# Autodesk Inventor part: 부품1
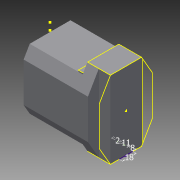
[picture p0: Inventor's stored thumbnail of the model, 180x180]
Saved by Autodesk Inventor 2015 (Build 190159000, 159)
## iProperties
Created: 2023-05
Part Number: 부품1
Material: 일반
Document SubType Name: Modeling
Designer: 102566
Density: 1 g/cm^3
Appearance: 기본값
Author: 102566
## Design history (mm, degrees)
sketch "스케치1"
  geometry: L1 (-35, -40)-(35, -40); L2 (35, -40)-(35, 40); L3 (35, 40)-(-35, 40); L4 (-35, 40)-(-35, -40); L5 (-35, -40)-(35, 40); L6 (35, -40)-(-35, 40); 1 further point
  constraints: 12 end point, 2 midpoint, 2 parallel, 1 horizontal, 1 perpendicular
  dimensions: "d0" = 70 distance of L3.end L2.end; "d1" = 80 distance of L2.end L1.end
extrude "돌출1" new body sketch "스케치1" distance "d2" = 70; taper "d3" = 0 deg
sketch "스케치2"
  geometry: L1 (40, 35)-(-40, 35) reference; L2 (-40, 35)-(-40, -35) reference; L3 (-40, -35)-(40, -35) reference; L4 (0, 35)-(-26, 35); L5 (-26, 35)-(-40, 26.917); L6 (0, -35)-(-26, -35); L7 (-26, -35)-(-40, -26.917); 1 further point
  constraints: 8 end point, 4 point on line, 2 midpoint
  dimensions: "d4" = 26 distance of L4.start L4.end; "d5" = 30 deg angle of L1 L5; "d6" = 26 distance of L6.start L6.end; "d7" = 30 deg angle of L3 L7
extrude "돌출2" cut sketch "스케치2" stored distance "d8" = 70; taper "d9" = 0 deg
sketch "스케치3"
  geometry: 1 further point
hole "구멍1" sketch "스케치3" at (0, 0) diameter "d10" = 60; stored, may be unused: countersink angle "d14" = 90 deg, drill point angle "d16" = 0 deg; dims "d11" = 6, "d12" = 4, "d13" = 2, "d15" = 5.8
sketch "스케치4"
  geometry: C1 r 30 at (0, 0) reference
hole "구멍2" sketch "스케치4" at (0, 0) diameter "d17" = 60; stored, may be unused: countersink angle "d21" = 90 deg, drill point angle "d23" = 0 deg; dims "d18" = 6, "d19" = 63, "d20" = 2.2, "d22" = 6
sketch "스케치5"
  geometry: 1 further point
sketch "스케치6"
  geometry: L1 (-8, -30)-(-8, -31.5) reference; L2 (-8, -31.5)-(-5.8, -31.5) reference; L3 (-5.8, -31.5)-(-5.8, -30) reference; L4 (-5.8, -30)-(0, -30) reference; L5 (0, -30)-(0, -40) reference; L6 (0, -40)-(-70, -40) reference; L7 (-70, -40)-(-70, 40) reference; L8 (-70, 40)-(0, 40) reference; L9 (0, 40)-(0, 30) reference; L10 (0, 30)-(-5.8, 30) reference; L11 (-5.8, 30)-(-5.8, 31.5) reference; L12 (-5.8, 31.5)-(-8, 31.5) reference; L13 (-8, 31.5)-(-8, 30) reference; L14 (-8, 30)-(-14, 30) reference; L15 (-14, 30)-(-14, -30) reference; L16 (-14, -30)-(-8, -30) reference; L17 (-70, -26)-(-70, 26) reference; L18 (-70, 0)-(0, 0); L19 (-14, -30)-(-14, 30) reference; L20 (-14, 0)-(-14, 25.786); L21 (-14, 25.786)-(-16.158, 25); L22 (-16.158, 25)-(-16.158, 0); L23 (-16.158, 0)-(-14, 0); 2 further points
  constraints: 10 end point, 4 midpoint, 2 point on line, 1 collinear, 1 horizontal, 1 perpendicular, 1 vertical alignment
  dimensions: "d27" = 2.15848 distance between parallel lines of L15 L22; "d28" = 25 distance of L21.end L22.end
revolve "회전1" sketch "스케치6" stored, may be unused: angle "d29" = 90 deg
sketch "스케치7"
  geometry: C1 r 25 at (0, 0) reference; C2 r 25 at (0, 0)
  constraints: 1 centre point, 1 coincident
  dimensions: "d30" = 50 diameter of C2
extrude "돌출3" cut sketch "스케치7" distance "d31" = 42.842; taper "d32" = 0 deg
sketch "스케치8"
  geometry: 1 further point
sketch "스케치9"
  geometry: 1 further point
sketch "스케치10"
  geometry: L1 (40, 26.917)-(26, 35) reference; L2 (26, 35)-(-26, 35) reference; L3 (-26, 35)-(-40, 26.917) reference; L4 (-40, 26.917)-(-40, -26.917) reference; L5 (-40, -26.917)-(-26, -35) reference; L6 (26, -35)-(40, -26.917) reference; L7 (40, -26.917)-(40, 26.917) reference; L8 (-26, 35)-(26, 35); L9 (51, 20.566)-(51, -20.566); L10 (26, -35)-(-26, -35); L11 (-51, -20.566)-(-51, 20.566); L12 (-51, 35)-(51, -35); L13 (51, 35)-(-51, -35); L14 (40, -26.917)-(51, -20.566); L15 (40, 26.917)-(51, 20.566); L16 (-40, -26.917)-(-51, -20.566); L17 (-40, 26.917)-(-51, 20.566); L18 (-40, 26.917)-(-26, 35) reference; C1 r 30 at (0, 0) reference; 1 further point
  constraints: 20 end point, 5 point on line, 2 midpoint, 2 parallel, 1 collinear, 1 horizontal, 1 perpendicular
  dimensions: "d33" = 102 distance of L12.end L13.end; "d34" = 60 deg angle of L15 L14; "d35" = 51 distance from line of point (0, 0) L9; "d36" = 60 deg angle of L17 L16; "d37" = 51 distance from line of point (0, 0) L11; "d38" = 35 distance from line of C1.centre L8
extrude "돌출4" join sketch "스케치10" distance "d39" = 30; taper "d40" = 0 deg
sketch "스케치11"
  geometry: L1 (70, 53.834)-(70, 0) reference; L2 (70, 0)-(0, 0) reference; L3 (70, 53.834)-(64, 53.834); L4 (64, 53.834)-(64, 0); L5 (64, 0)-(70, 0); L6 (70, 0)-(70, 53.834); 1 further point
  constraints: 8 end point, 2 parallel, 1 horizontal, 1 perpendicular, 1 point on line
  dimensions: "d41" = 6 distance of L5.end L4.end
extrude "돌출5" join sketch "스케치11" distance "d42" = 2; taper "d43" = 0 deg
sketch "스케치12"
  geometry: L1 (26, -35)-(51, -20.566) reference; L2 (51, -20.566)-(51, 20.566) reference; L3 (51, 20.566)-(26, 35) reference; L4 (26, 35)-(-26, 35) reference; L5 (-26, 35)-(-51, 20.566) reference; L6 (-51, 20.566)-(-51, -20.566) reference; L7 (-51, -20.566)-(-26, -35) reference; L8 (-26, -35)-(26, -35) reference; 1 further point
sketch "스케치13"
  geometry: L1 (30, 41.132)-(30, 0) reference; L2 (30, 42.566)-(30, -1.434); L3 (30, 42.566)-(15, 42.566); L4 (15, 42.566)-(15, 55.566); L5 (-70, 55.566)-(30, 55.566) reference; L6 (30, 42.566)-(30, 55.566); L7 (30, 55.566)-(30, 41.132) reference; 2 further points
  constraints: 8 end point, 2 midpoint, 1 collinear, 1 horizontal, 1 perpendicular, 1 point on line, 1 vertical
  dimensions: "d44" = 44 distance of L2.start L2.end; "d45" = 15 distance of L2.start L3.end
extrude "돌출6" cut sketch "스케치13" stored distance "d46" = 2; taper "d47" = 0 deg
sketch "스케치14"
  geometry: L1 (70, 53.834)-(64, 53.834) reference; L2 (64, 53.834)-(64, 0) reference; L3 (64, 0)-(70, 0) reference; L4 (70, 0)-(70, 1.155) reference; L5 (70, 52.679)-(70, 1.155) reference; L6 (70, 52.679)-(70, 53.834) reference; 1 further point
sketch "스케치15"
  geometry: L1 (0, 41.132)-(0, 0) reference; L2 (0, 0)-(30, 0) reference; L3 (30, 41.132)-(30, 0) reference; L4 (0, 41.132)-(30, 41.132) reference; 1 further point
sketch "스케치16"
  geometry: L1 (48.517, 22)-(-48.517, 22) reference; L2 (-48.517, 22)-(-51, 20.566) reference; L3 (-51, 20.566)-(-51, -20.566) reference; L4 (-51, -20.566)-(-26, -35) reference; L5 (-26, -35)-(26, -35) reference; L6 (26, -35)-(51, -20.566) reference; L7 (51, -20.566)-(51, 20.566) reference; L8 (51, 20.566)-(48.517, 22) reference; 1 further point
sketch "스케치17"
  geometry: L1 (0, 0)-(30, 0) reference; L2 (30, 0)-(15, 0); L3 (30, 0)-(30, -14.434); L4 (30, 0)-(30, -14.434) reference; L5 (30, -14.434)-(15, -14.434); L6 (15, -14.434)-(15, 0); 1 further point
  constraints: 8 end point, 2 perpendicular, 1 collinear, 1 midpoint
  dimensions: "d48" = 15 distance of L1.end L2.end
extrude "돌출7" cut sketch "스케치17" stored distance "d49" = 2; taper "d50" = 0 deg
sketch "스케치18"
  geometry: L1 (0, 0)-(0, 41.132) reference; L2 (0, 41.132)-(-30, 41.132) reference; L3 (-30, 0)-(-30, 41.132) reference; L4 (-15, 0)-(-30, 0) reference; L5 (0, 0)-(-15, 0) reference; L6 (-30, 11.566)-(-30, 29.566); L7 (-30, 29.566)-(-22, 29.566); L8 (-22, 29.566)-(-21.046, 31.233); L9 (-21.046, 31.233)-(-10.046, 31.233); L10 (-10.046, 31.233)-(-8.731, 29.566); L11 (-8.731, 29.566)-(-6.731, 29.566); 2 further points
  constraints: 12 end point, 3 horizontal, 2 midpoint, 1 horizontal alignment, 1 vertical
  dimensions: "d51" = 18 distance of L6.start L6.end; "d52" = 8 distance of L6.end L7.end; "d53" = 11 distance of L8.end L9.end; "d54" = 2 distance of L10.end L11.end
node "솔리드1"
mirror "대칭1"
node "절단 모서리 투영1"
